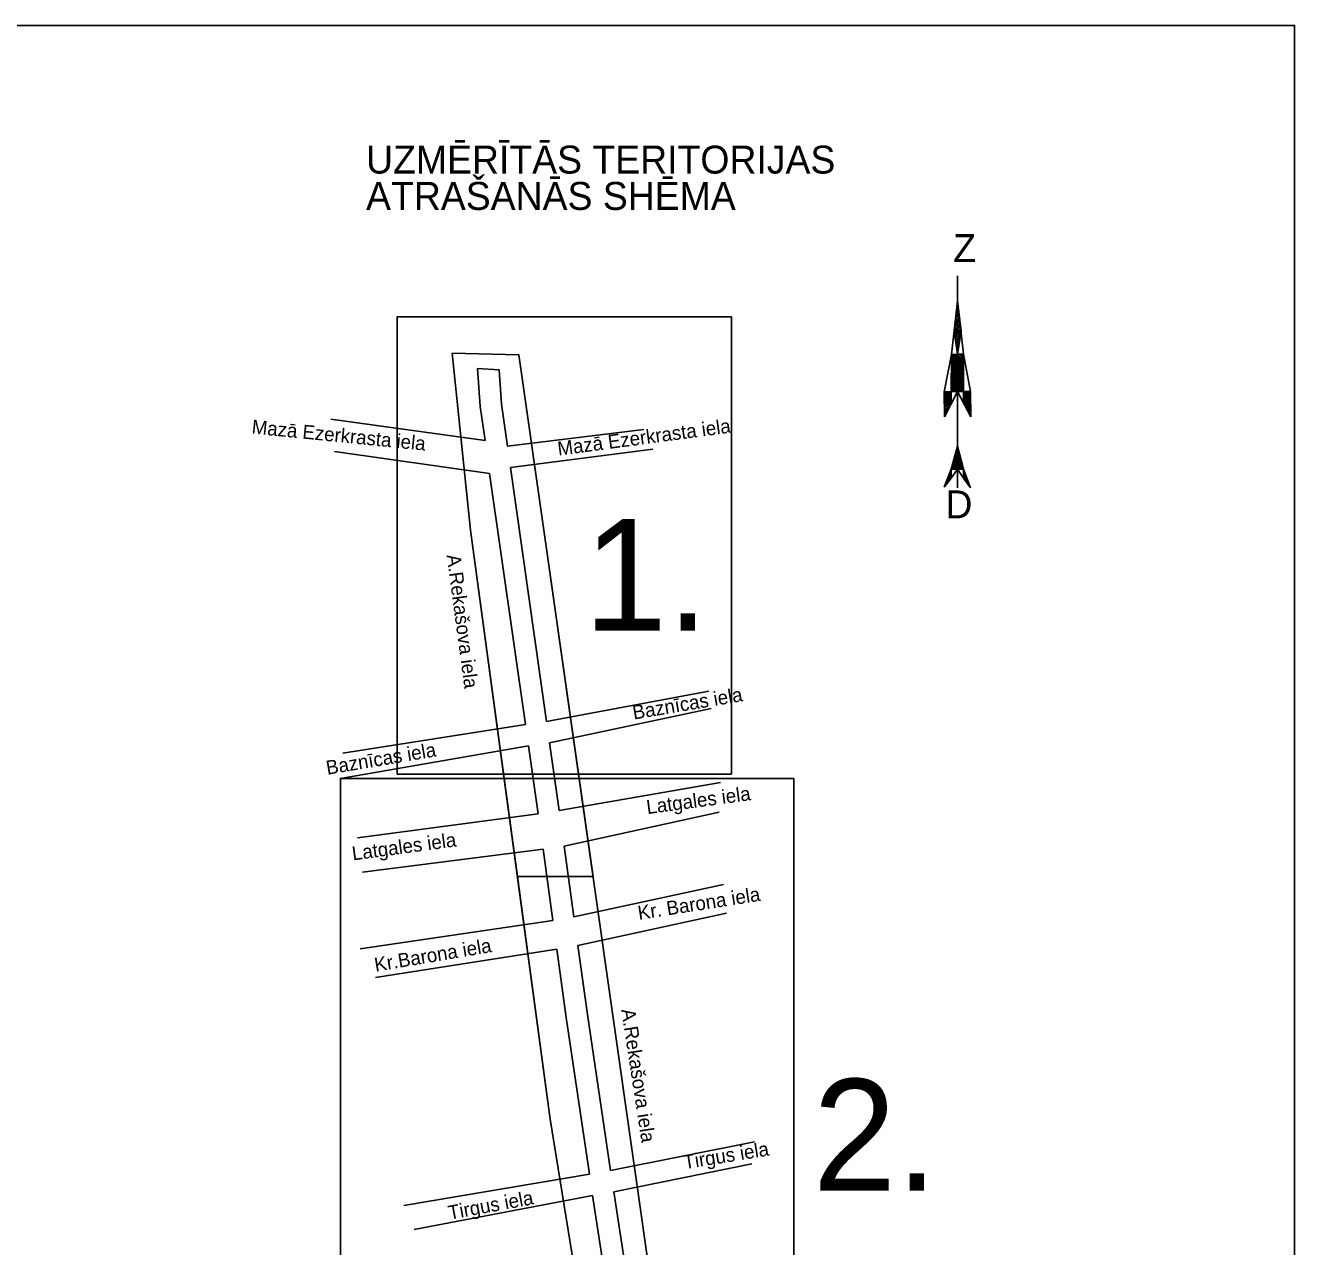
# Model space of a CAD drawing. Extents: x 728710 to 728960, y 272811 to 273475.
# Drawn here: x 728914.1 to 728959.52, y 273158.36 to 273202.05 of the extents above; entities that cross this region are included whole.
import ezdxf

# ---------------------------------------------------------------- set-up
doc = ezdxf.new("R2010")
doc.units = 0
doc.layers.add('RAMI_PLAN_####_TKST_#', color=7, linetype='Continuous')

msp = doc.modelspace()

# ---------------------------------------------------------------- linework, layer by layer
at = {"layer": 'RAMI_PLAN_####_TKST_#'}
for p, q in [((728947.46, 273193.084), (728947.459, 273192.204)), ((728947.241, 273190.279), (728947.46, 273192.195)), ((728947.46, 273192.195), (728947.335, 273191.106)), ((728947.451, 273192.119), (728947.467, 273192.134)), ((728947.458, 273192.183), (728947.461, 273192.185)), ((728947.46, 273192.195), (728947.675, 273190.285)), ((728947.582, 273191.109), (728947.46, 273192.195)), ((728947.385, 273191.544), (728947.518, 273191.677)), ((728947.393, 273191.608), (728947.512, 273191.728)), ((728947.4, 273191.672), (728947.507, 273191.779)), ((728947.407, 273191.736), (728947.501, 273191.829)), ((728947.414, 273191.799), (728947.495, 273191.88)), ((728947.422, 273191.863), (728947.489, 273191.931)), ((728947.429, 273191.927), (728947.484, 273191.982)), ((728947.436, 273191.991), (728947.478, 273192.033)), ((728947.444, 273192.055), (728947.472, 273192.084)), ((728947.336, 273191.099), (728947.558, 273191.321)), ((728947.342, 273191.161), (728947.552, 273191.372)), ((728947.344, 273191.05), (728947.564, 273191.27)), ((728947.349, 273191.225), (728947.547, 273191.423)), ((728947.351, 273191), (728947.57, 273191.219)), ((728947.356, 273191.289), (728947.541, 273191.473)), ((728947.363, 273191.352), (728947.535, 273191.524)), ((728947.371, 273191.416), (728947.53, 273191.575)), ((728947.378, 273191.48), (728947.524, 273191.626)), ((728947.457, 273190.282), (728947.335, 273191.106)), ((728947.335, 273191.106), (728947.457, 273190.282)), ((728947.358, 273190.951), (728947.575, 273191.168)), ((728947.365, 273190.902), (728947.581, 273191.118)), ((728947.373, 273190.853), (728947.574, 273191.053)), ((728947.38, 273190.803), (728947.563, 273190.987)), ((728947.387, 273190.754), (728947.553, 273190.92)), ((728947.394, 273190.705), (728947.543, 273190.854)), ((728947.402, 273190.655), (728947.533, 273190.787)), ((728947.582, 273191.109), (728947.457, 273190.282)), ((728947.457, 273190.282), (728947.582, 273191.109)), ((728947.409, 273190.606), (728947.523, 273190.72)), ((728947.416, 273190.557), (728947.513, 273190.654)), ((728947.424, 273190.507), (728947.503, 273190.587)), ((728947.431, 273190.458), (728947.493, 273190.52)), ((728947.438, 273190.409), (728947.483, 273190.454)), ((728947.445, 273190.36), (728947.473, 273190.387)), ((728947.453, 273190.31), (728947.463, 273190.32)), ((728946.974, 273188.943), (728947.241, 273190.279)), ((728947.241, 273190.279), (728947.232, 273188.963)), ((728947.237, 273189.78), (728947.457, 273189.999)), ((728947.237, 273189.723), (728947.456, 273189.943)), ((728947.237, 273189.666), (728947.456, 273189.886)), ((728947.238, 273189.894), (728947.457, 273190.112)), ((728947.238, 273189.837), (728947.457, 273190.056)), ((728947.239, 273190.065), (728947.457, 273190.282)), ((728947.239, 273190.008), (728947.457, 273190.226)), ((728947.239, 273189.951), (728947.457, 273190.169)), ((728947.24, 273190.179), (728947.342, 273190.281)), ((728947.24, 273190.122), (728947.399, 273190.281)), ((728947.241, 273190.279), (728947.457, 273190.282)), ((728947.241, 273190.236), (728947.285, 273190.28)), ((728947.457, 273190.282), (728947.452, 273185.506)), ((728947.456, 273189.984), (728947.674, 273189.767)), ((728947.456, 273189.928), (728947.674, 273189.71)), ((728947.456, 273189.871), (728947.674, 273189.654)), ((728947.457, 273190.282), (728947.675, 273190.285)), ((728947.457, 273190.267), (728947.674, 273190.049)), ((728947.457, 273190.21), (728947.674, 273189.993)), ((728947.457, 273190.154), (728947.674, 273189.936)), ((728947.457, 273190.097), (728947.674, 273189.88)), ((728947.457, 273190.041), (728947.674, 273189.823)), ((728947.497, 273190.283), (728947.674, 273190.106)), ((728947.553, 273190.283), (728947.675, 273190.162)), ((728947.609, 273190.284), (728947.675, 273190.219)), ((728947.665, 273190.285), (728947.675, 273190.275)), ((728947.675, 273190.285), (728947.673, 273188.96)), ((728947.675, 273190.285), (728947.917, 273188.955)), ((728931.05, 273189.72), (728930.276, 273189.775)), ((728947.233, 273189.21), (728947.456, 273189.433)), ((728947.234, 273189.324), (728947.456, 273189.546)), ((728947.234, 273189.267), (728947.456, 273189.49)), ((728947.235, 273189.495), (728947.456, 273189.716)), ((728947.235, 273189.438), (728947.456, 273189.659)), ((728947.235, 273189.381), (728947.456, 273189.603)), ((728947.236, 273189.609), (728947.456, 273189.829)), ((728947.236, 273189.552), (728947.456, 273189.773)), ((728947.456, 273189.815), (728947.674, 273189.597)), ((728947.456, 273189.758), (728947.674, 273189.541)), ((728947.456, 273189.702), (728947.674, 273189.484)), ((728947.456, 273189.645), (728947.674, 273189.428)), ((728947.456, 273189.589), (728947.674, 273189.371)), ((728947.456, 273189.532), (728947.673, 273189.315)), ((728947.456, 273189.476), (728947.673, 273189.258)), ((728947.456, 273189.419), (728947.673, 273189.202)), ((728946.974, 273188.943), (728947.455, 273188.949)), ((728947.232, 273188.946), (728946.974, 273188.943)), ((728946.974, 273188.943), (728946.987, 273188.049)), ((728946.974, 273188.943), (728946.987, 273188.049)), ((728946.975, 273188.894), (728947.025, 273188.943)), ((728946.976, 273188.838), (728947.082, 273188.944)), ((728946.977, 273188.782), (728947.139, 273188.945)), ((728946.978, 273188.727), (728947.196, 273188.946)), ((728946.987, 273188.049), (728947.455, 273188.949)), ((728947.232, 273189.039), (728947.456, 273189.263)), ((728947.232, 273188.982), (728947.456, 273189.206)), ((728947.232, 273188.519), (728947.232, 273188.963)), ((728947.232, 273188.519), (728947.232, 273188.946)), ((728947.233, 273189.153), (728947.456, 273189.376)), ((728947.233, 273189.096), (728947.456, 273189.32)), ((728947.252, 273188.946), (728947.456, 273189.15)), ((728947.31, 273188.947), (728947.456, 273189.093)), ((728947.367, 273188.948), (728947.456, 273189.037)), ((728947.424, 273188.949), (728947.455, 273188.98)), ((728947.455, 273189.024), (728947.529, 273188.95)), ((728947.455, 273188.967), (728947.473, 273188.949)), ((728947.455, 273188.949), (728947.917, 273188.955)), ((728947.93, 273188.049), (728947.455, 273188.949)), ((728947.456, 273189.363), (728947.673, 273189.145)), ((728947.456, 273189.306), (728947.673, 273189.089)), ((728947.456, 273189.25), (728947.673, 273189.032)), ((728947.456, 273189.193), (728947.673, 273188.976)), ((728947.456, 273189.137), (728947.641, 273188.951)), ((728947.456, 273189.08), (728947.585, 273188.951)), ((728947.67, 273188.543), (728947.673, 273188.96)), ((728947.673, 273188.952), (728947.67, 273188.543)), ((728947.917, 273188.955), (728947.673, 273188.952)), ((728947.673, 273188.946), (728947.921, 273188.698)), ((728947.723, 273188.953), (728947.92, 273188.756)), ((728947.779, 273188.953), (728947.919, 273188.813)), ((728947.835, 273188.954), (728947.918, 273188.87)), ((728947.891, 273188.955), (728947.918, 273188.928)), ((728947.93, 273188.049), (728947.917, 273188.955)), ((728947.93, 273188.049), (728947.917, 273188.955)), ((728946.978, 273188.671), (728947.232, 273188.924)), ((728946.979, 273188.615), (728947.232, 273188.868)), ((728946.98, 273188.559), (728947.232, 273188.811)), ((728946.981, 273188.504), (728947.232, 273188.755)), ((728946.982, 273188.448), (728947.232, 273188.698)), ((728946.982, 273188.392), (728947.232, 273188.641)), ((728946.983, 273188.336), (728947.232, 273188.585)), ((728946.984, 273188.281), (728947.232, 273188.528)), ((728946.987, 273188.049), (728947.232, 273188.519)), ((728947.67, 273188.609), (728947.926, 273188.354)), ((728947.67, 273188.553), (728947.927, 273188.296)), ((728947.67, 273188.543), (728947.93, 273188.049)), ((728947.671, 273188.722), (728947.924, 273188.469)), ((728947.671, 273188.665), (728947.925, 273188.411)), ((728947.672, 273188.89), (728947.922, 273188.641)), ((728947.672, 273188.834), (728947.923, 273188.583)), ((728947.672, 273188.778), (728947.923, 273188.526)), ((728946.985, 273188.225), (728947.181, 273188.421)), ((728946.986, 273188.169), (728947.119, 273188.303)), ((728946.986, 273188.113), (728947.058, 273188.185)), ((728946.987, 273188.058), (728946.997, 273188.067)), ((728947.721, 273188.445), (728947.927, 273188.239)), ((728947.784, 273188.326), (728947.928, 273188.182)), ((728947.847, 273188.206), (728947.929, 273188.124)), ((728947.911, 273188.086), (728947.93, 273188.067)), ((728947.452, 273186.989), (728947.232, 273186.169)), ((728947.345, 273186.591), (728947.453, 273186.699)), ((728947.366, 273186.668), (728947.453, 273186.756)), ((728947.386, 273186.745), (728947.453, 273186.812)), ((728947.407, 273186.823), (728947.453, 273186.869)), ((728947.428, 273186.9), (728947.453, 273186.925)), ((728947.449, 273186.977), (728947.453, 273186.982)), ((728947.452, 273186.989), (728947.673, 273186.169)), ((728947.453, 273186.965), (728947.46, 273186.958)), ((728947.453, 273186.909), (728947.481, 273186.881)), ((728947.453, 273186.852), (728947.502, 273186.803)), ((728947.453, 273186.796), (728947.523, 273186.726)), ((728947.453, 273186.739), (728947.544, 273186.648)), ((728947.453, 273186.683), (728947.565, 273186.571)), ((728947.241, 273186.204), (728947.453, 273186.416)), ((728947.262, 273186.281), (728947.453, 273186.472)), ((728947.263, 273186.17), (728947.453, 273186.359)), ((728947.283, 273186.359), (728947.453, 273186.529)), ((728947.303, 273186.436), (728947.453, 273186.586)), ((728947.321, 273186.17), (728947.453, 273186.303)), ((728947.324, 273186.513), (728947.453, 273186.642)), ((728947.378, 273186.171), (728947.453, 273186.246)), ((728947.453, 273186.626), (728947.586, 273186.493)), ((728947.453, 273186.57), (728947.606, 273186.416)), ((728947.453, 273186.513), (728947.627, 273186.339)), ((728947.453, 273186.456), (728947.648, 273186.261)), ((728947.453, 273186.4), (728947.669, 273186.184)), ((728947.453, 273186.343), (728947.626, 273186.17)), ((728947.453, 273186.287), (728947.569, 273186.171)), ((728947.453, 273186.23), (728947.511, 273186.172)), ((728946.977, 273185.522), (728947.232, 273186.169)), ((728947.232, 273186.169), (728946.977, 273185.522)), ((728947.232, 273185.85), (728946.977, 273185.522)), ((728946.977, 273185.522), (728947.232, 273185.85)), ((728947.021, 273185.634), (728947.212, 273185.825)), ((728947.058, 273185.727), (728947.232, 273185.901)), ((728947.095, 273185.821), (728947.232, 273185.958)), ((728947.131, 273185.914), (728947.232, 273186.014)), ((728947.168, 273186.007), (728947.232, 273186.071)), ((728947.205, 273186.1), (728947.232, 273186.127)), ((728947.232, 273186.169), (728947.453, 273186.173)), ((728947.232, 273185.85), (728947.453, 273186.173)), ((728947.232, 273186.169), (728947.232, 273185.85)), ((728947.232, 273185.85), (728947.232, 273186.169)), ((728947.436, 273186.172), (728947.453, 273186.189)), ((728947.453, 273186.174), (728947.454, 273186.173)), ((728947.673, 273186.169), (728947.453, 273186.173)), ((728947.453, 273186.173), (728947.673, 273185.855)), ((728947.673, 273186.169), (728947.921, 273185.506)), ((728947.673, 273185.855), (728947.673, 273186.169)), ((728947.921, 273185.506), (728947.673, 273186.169)), ((728947.673, 273186.169), (728947.673, 273185.855)), ((728947.673, 273186.167), (728947.674, 273186.165)), ((728947.673, 273186.11), (728947.708, 273186.075)), ((728947.673, 273186.054), (728947.742, 273185.985)), ((728947.673, 273185.997), (728947.776, 273185.894)), ((728947.673, 273185.941), (728947.81, 273185.804)), ((728947.673, 273185.884), (728947.843, 273185.714)), ((728947.921, 273185.506), (728947.673, 273185.855)), ((728947.673, 273185.855), (728947.921, 273185.506)), ((728946.985, 273185.541), (728947.017, 273185.573)), ((728947.741, 273185.76), (728947.877, 273185.623)), ((728947.88, 273185.564), (728947.911, 273185.533)), ((728934.416, 273171.599), (728932.739, 273183.403)), ((728931.708, 273171.599), (728934.416, 273171.599)), ((728934.416, 273171.599), (728931.708, 273171.599)), ((728931.708, 273171.599), (728932.88, 273162.918))]:
    msp.add_line(p, q, dxfattribs=at)
for points in [[(728709.938, 272811.037), (728959.516, 272811.036), (728959.516, 273202.048), (728709.939, 273202.048)], [(728939.366, 273191.619), (728927.406, 273191.619), (728927.406, 273175.262), (728939.366, 273175.262)], [(728934.464, 273153.138), (728937.117, 273153.643), (728936.526, 273156.75), (728934.42, 273171.567), (728932.739, 273183.403), (728931.765, 273190.258), (728929.379, 273190.325), (728930.036, 273183.984), (728932.88, 273162.918)], [(728941.598, 273175.11), (728925.379, 273175.11), (728925.379, 273151.579), (728941.598, 273151.579)]]:
    msp.add_lwpolyline(points, close=True, dxfattribs=at)
for points in [[(728932.739, 273183.403), (728931.765, 273190.258), (728929.379, 273190.325), (728930.036, 273183.984), (728931.708, 273171.599)], [(728930.55, 273187.198), (728930.38, 273188.409), (728930.276, 273189.775)], [(728931.355, 273186.991), (728931.144, 273188.492), (728931.05, 273189.72)], [(728930.55, 273187.198), (728925.029, 273187.966)], [(728936.23, 273187.593), (728931.355, 273186.991)], [(728930.716, 273186.022), (728925.16, 273186.804)], [(728936.559, 273186.891), (728931.463, 273186.228)], [(728932.754, 273177.147), (728931.463, 273186.228)], [(728931.995, 273177.034), (728930.716, 273186.022)], [(728932.754, 273177.147), (728938.554, 273178.225)], [(728932.862, 273176.386), (728938.642, 273177.611)], [(728931.995, 273177.034), (728925.467, 273176.01)], [(728932.103, 273176.274), (728925.379, 273175.11)], [(728932.103, 273176.274), (728932.448, 273173.846)], [(728932.862, 273176.386), (728933.208, 273173.954)], [(728938.97, 273174.957), (728933.208, 273173.954)], [(728932.448, 273173.846), (728925.993, 273172.982)], [(728938.927, 273173.904), (728933.385, 273172.686)], [(728933.385, 273172.686), (728933.733, 273170.15)], [(728932.625, 273172.579), (728926.168, 273171.753)], [(728932.625, 273172.579), (728932.976, 273170.018)], [(728932.88, 273162.918), (728934.464, 273153.138), (728937.117, 273153.643), (728936.526, 273156.75), (728934.42, 273171.567), (728934.416, 273171.599)], [(728939.08, 273171.315), (728933.733, 273170.15)], [(728932.976, 273170.018), (728926.081, 273169.011)], [(728939.19, 273170.284), (728933.872, 273169.135)], [(728933.115, 273169.003), (728926.629, 273167.98)], [(728933.115, 273169.003), (728933.451, 273166.553), (728934.283, 273160.945)], [(728933.872, 273169.135), (728934.211, 273166.661), (728935.039, 273161.078)], [(728940.186, 273162.111), (728935.039, 273161.078)], [(728940.098, 273161.321), (728935.154, 273160.318)], [(728934.283, 273160.945), (728927.647, 273159.83)], [(728934.398, 273160.185), (728928.019, 273158.974)], [(728934.398, 273160.185), (728935.197, 273155.011)], [(728935.154, 273160.318), (728935.951, 273155.16)]]:
    msp.add_lwpolyline(points, dxfattribs=at)

# ---------------------------------------------------------------- texts
for s, height, rotation, p in [('UZMĒRĪTĀS TERITORIJAS ', 1, 359.9999, (728926.294, 273196.747)), ('ATRAŠANĀS SHĒMA', 1, 359.9999, (728926.294, 273195.447)), ('Z', 1, 359.9999, (728947.302, 273193.581)), ('Mazā Ezerkrasta iela', 0.5, 354.3726, (728922.187, 273187.447)), ('Mazā Ezerkrasta iela', 0.5, 7.6235, (728933.177, 273186.653)), ('D', 1, 359.9999, (728947.024, 273184.413)), ('A.Rekašova iela', 0.5, 277.641, (728929.175, 273183.091)), ('Baznīcas iela', 0.5, 9.6084, (728935.873, 273177.212)), ('Baznīcas iela', 0.5, 9.6084, (728924.907, 273175.236)), ('Latgales iela', 0.5, 7.723, (728936.359, 273173.828)), ('Latgales iela', 0.5, 7.723, (728925.824, 273172.172)), ('Kr. Barona iela', 0.5, 8.9676, (728936.057, 273170.044)), ('Kr.Barona iela', 0.5, 9.638, (728926.635, 273168.189)), ('A.Rekašova iela', 0.5, 278.74, (728935.421, 273166.83)), ('Tirgus iela', 0.5, 9.194, (728937.692, 273161.125)), ('Tirgus iela', 0.5, 10.472, (728929.28, 273159.316))]:
    msp.add_text(s, height=height, rotation=rotation, dxfattribs=at).set_placement(p)
for s, p in [('1.', (728934.088, 273180.391)), ('2.', (728942.282, 273160.353))]:
    msp.add_text(s, height=4, dxfattribs=at).set_placement(p)

doc.saveas('drawing.dxf')
